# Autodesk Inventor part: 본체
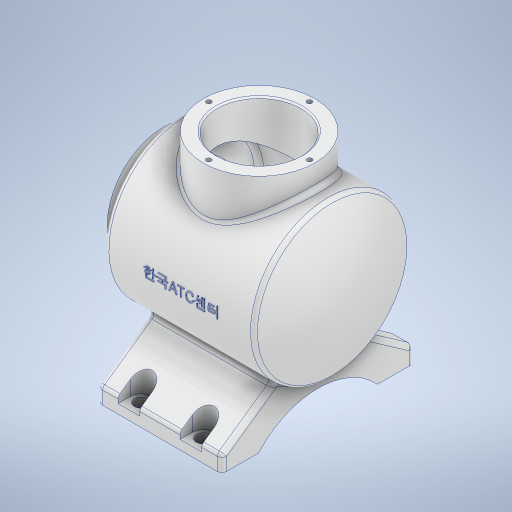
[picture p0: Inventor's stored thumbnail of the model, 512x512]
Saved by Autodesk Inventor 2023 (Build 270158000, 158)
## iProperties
Created: 2023-12
Part Number: 본체
Material: 알루미늄 6061
Document SubType Name: Modeling
Designer: asung
Density: 2.7 g/cm^3
Appearance: 알루미늄 - 평지
Mass: 1296.7 g
Surface Area: 1060.42 cm^2
Volume: 480.26 cm^3
Author: asung
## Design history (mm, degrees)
sketch "스케치2"
  geometry: L1 (0, 0)-(108, 0); L2 (0, 0)-(0, 50); L3 (0, 50)-(96.336, 50); L4 (108, 0)-(-5, 0); A1 r 113 centre (-5, 0) between (108, 0) and (96.336, 50)
  constraints: 8 end point, 2 horizontal, 2 point on circle, 1 centre point, 1 coincident, 1 perpendicular, 1 vertical
  dimensions: "d6" = 108 distance of L1.start L1.end; "d7" = 100 diameter of L3 L1; "d9" = 226 diameter of A1
revolve "회전2" sketch "스케치2" stored, may be unused: angle "d10" = 90 deg
fillet "모깎기1" dims "d11" = 3
sketch "스케치3"
  geometry: C1 r 36 at (0, 0); 1 further point
  constraints: 1 centre point, 1 coincident
  dimensions: "d12" = 72 diameter of C1
extrude "돌출1" join sketch "스케치3" distance "d13" = 12; taper "d14" = 0 deg
fillet "모깎기2" dims "d15" = 3
node "작업 평면1"
sketch "스케치4"
  geometry: L1 (0, 0)-(0, -77); L2 (0, -77)-(-62, -77); L3 (0, -77)-(62, -77); L4 (-62, -77)-(-62, -67); L5 (62, -77)-(62, -67); L6 (62, -67)-(24.84, -40.98); L7 (-62, -67)-(-25.197, -41.23); L8 (0, -77)-(0, -60); L9 (0, -77)-(38.5, -77); L10 (0, -77)-(-38.5, -77); C1 r 50 at (0, 0) reference; A1 r 52.096 centre (0, -112.096) between (38.5, -77) and (-38.5, -77); 3 further points
  constraints: 20 end point, 3 point on circle, 3 point on line, 3 vertical, 2 horizontal, 1 centre point
  dimensions: "d17" = 77 distance of L1.start L1.end; "d18" = 62 distance of L1.end L2.end; "d19" = 62 distance of L1.end L3.end; "d20" = 10 distance of L2.end L4.end; "d21" = 10 distance of L3.end L5.end; "d22" = 55 deg angle of L5 L6; "d23" = 55 deg angle of L4 L7; "d24" = 17 distance of L1.end L8.end; "d25" = 38.5 distance of L1.end L9.end; "d26" = 38.5 distance of L1.end L10.end
extrude "돌출2" join sketch "스케치4" distance "d27" = 80; taper "d28" = 0 deg
node "작업 평면2"
sketch "스케치5"
  geometry: L1 (-5, 12)-(86.454, 12) reference; L2 (-20, 98)-(-20, 26) reference; L3 (-20, 62)-(42, 62); C1 r 36 at (42, 62); 1 further point
  constraints: 2 end point, 1 centre point, 1 coincident, 1 horizontal, 1 midpoint
  dimensions: "d30" = 62 distance of L3.start L3.end; "d31" = 72 diameter of C1
extrude "돌출3" join sketch "스케치5" stored distance "d32" = 80; taper "d33" = 0 deg
sketch "스케치6"
  geometry: L1 (0, 23.5)-(0, -11.806) reference; L2 (0, 23.5)-(0, 15.5); L3 (0, 15.5)-(20, 15.5); L4 (0, 23.5)-(80, 23.5) reference; L5 (20, 15.5)-(60, 15.5); 1 further point
  constraints: 6 end point, 2 horizontal, 1 point on line
  dimensions: "d34" = 8 distance of L1.start L2.end; "d35" = 20 distance of L2.end L3.end; "d37" = 40 distance of L3.end L5.end
hole "구멍1" sketch "스케치6" at (20, 15.5), (60, 15.5) diameter "d38" = 9; stored, may be unused: countersink angle "d42" = 90 deg, drill point angle "d44" = 0 deg; dims "d39" = 8, "d40" = 4, "d41" = 2, "d43" = 6
sketch "스케치7"
  geometry: C1 r 4.5 at (0, 0) reference; 1 further point
  node "투영된 루프1"
sketch "스케치8"
  geometry: L1 (94.454, -50)-(88, -50) reference; L2 (88, -50)-(88, -60) reference; L3 (88, -60)-(8, -60) reference; L4 (8, -60)-(8, -50) reference; L5 (8, -50)-(3, -50) reference; L6 (0, -47)-(0, -39) reference; L7 (-3, -36)-(-12, -36) reference; L8 (-12, -36)-(-12, 36) reference; L9 (-12, 36)-(-3, 36) reference; L10 (0, 39)-(0, 47) reference; L11 (3, 50)-(14, 50) reference; L12 (14, 50)-(14, 65) reference; L13 (14, 65)-(86, 65) reference; L14 (86, 65)-(86, 50) reference; L15 (86, 50)-(94.454, 50) reference; L16 (89.916, 43)-(79, 43); L17 (21, 43)-(10, 43); L18 (7, 43)-(7, 39); L19 (79, 43)-(21, 43); L20 (7, 40)-(7, 0); L21 (7, 0)-(101, 0); A1 r 3 centre (94.454, 47) between (97.166, 48.282) and (94.454, 50) reference; A2 r 113 centre (-5, 0) between (97.166, -48.282) and (97.166, 48.282) reference; A3 r 3 centre (94.454, -47) between (94.454, -50) and (97.166, -48.282) reference; A4 r 3 centre (3, -47) between (0, -47) and (3, -50) reference; A5 r 3 centre (-3, -39) between (0, -39) and (-3, -36) reference; A6 r 3 centre (-3, 39) between (-3, 36) and (0, 39) reference; A7 r 3 centre (3, 47) between (3, 50) and (0, 47) reference; A8 r 106 centre (-5, 0) between (101, 0) and (92.68, 41.165); A9 r 3 centre (10, 40) between (10, 43) and (7, 40); A10 r 3 centre (89.916, 40) between (92.68, 41.165) and (89.916, 43); 3 further points
  constraints: 12 end point, 7 point on circle, 4 tangent, 3 centre point, 3 point on line, 1 horizontal, 1 vertical
  dimensions: "d45" = 3 radius of A9; "d46" = 7 radial gap between concentric circles of A2 A8; "d47" = 3 radius of A10 (derived); "d48" = 7 distance between parallel lines of L17 L11; "d49" = 7 distance between parallel lines of L10 L20
revolve "회전3" sketch "스케치8" stored, may be unused: angle "d50" = 90 deg
sketch "스케치9"
  geometry: 1 further point
hole "구멍2" sketch "스케치9" at (0, 0) diameter "d51" = 54; stored, may be unused: countersink angle "d55" = 90 deg, drill point angle "d57" = 0 deg; dims "d52" = 6, "d53" = 4, "d54" = 2, "d56" = 19
chamfer "모따기1" distance "d58" = 1; stored, may be unused: second distance "d59" = 2, angle "d60" = 45 deg
sketch "스케치10"
  geometry: C1 r 36 at (0, 0) reference; 1 further point
hole "구멍3" sketch "스케치10" at (0, 0) diameter "d61" = 54; stored, may be unused: countersink angle "d65" = 90 deg, drill point angle "d67" = 0 deg; dims "d62" = 6, "d63" = 4, "d64" = 2, "d66" = 25
sketch "스케치11"
  geometry: L1 (21.909, 15.78)-(-21.909, 15.78) reference; A1 r 27 centre (0, 0) between (21.909, 15.78) and (-21.909, 15.78) reference; 1 further point
hole "구멍4" sketch "스케치11" at (0, 0) diameter "d68" = 54; stored, may be unused: countersink angle "d72" = 90 deg, drill point angle "d74" = 0 deg; dims "d69" = 6, "d70" = 4, "d71" = 2, "d73" = 25
chamfer "모따기2" distance "d75" = 1; stored, may be unused: second distance "d76" = 2, angle "d77" = 45 deg
fillet "모깎기3" dims "d78" = 3
node "작업 평면3"
sketch "스케치12"
  geometry: L1 (-60.168, 36)-(-60.168, -36) reference; 2 further points
  constraints: 1 horizontal alignment, 1 other
  dimensions: "d79" = 62 distance from line of L1 point (1.832, 0)
feature "엠보싱1" sketch "스케치12" dims "d80" = 0.5, "d81" = 0
sketch "스케치13"
  geometry: L1 (0, 32.5)-(0, -32.5); A1 r 32.5 centre (0, 0) between (0, 32.5) and (0, -32.5); 1 further point
  constraints: 2 end point, 2 point on circle, 1 centre point, 1 coincident, 1 vertical
  dimensions: "d82" = 65 diameter of A1
hole "구멍5" sketch "스케치13" at (0, 32.5) diameter "d83" = 3.242; stored, may be unused: countersink angle "d87" = 90 deg, drill point angle "d89" = 118 deg; dims "d84" = 8, "d85" = 4, "d86" = 2, "d88" = 10
sketch "스케치14"
  geometry: L1 (0, 32.5)-(0, -32.5); C1 r 36 at (0, 0) reference; C2 r 28 at (0, 0) reference; A1 r 32.5 centre (0, 0) between (0, 32.5) and (0, -32.5); 1 further point
  constraints: 2 end point, 2 point on circle, 1 centre point, 1 coincident, 1 vertical
  dimensions: "d93" = 65 diameter of A1
hole "구멍6" sketch "스케치14" at (0, 32.5) diameter "d94" = 3.242; stored, may be unused: countersink angle "d98" = 90 deg, drill point angle "d100" = 118 deg; dims "d95" = 8, "d96" = 4, "d97" = 2, "d99" = 10
node "작업 평면4"
sketch "스케치15"
  geometry: L1 (80, -100.5)-(0, -100.5) reference; L2 (0, -100.5)-(0, -70.517) reference; L3 (0, -70.517)-(80, -70.517) reference; L4 (80, -70.517)-(80, -100.5) reference; L5 (0, 23.5)-(80, 23.5) reference; L6 (80, 23.5)-(80, -6.483) reference; L7 (80, -6.483)-(0, -6.483) reference; L8 (0, -6.483)-(0, 23.5) reference; L9 (13, 15.5)-(13, 23.5); L10 (0, 23.5)-(80, 23.5) reference; L11 (27, 15.5)-(27, 23.5); L12 (53, 15.5)-(53, 23.5); L13 (67, 15.5)-(67, 23.5); C1 r 4.5 at (20, 15.5) reference; C2 r 4.5 at (60, 15.5) reference; A1 r 7 centre (20, 15.5) between (13, 15.5) and (27, 15.5); A2 r 7 centre (60, 15.5) between (53, 15.5) and (67, 15.5); 5 further points
  constraints: 8 end point, 4 perpendicular, 4 point on circle, 4 point on line, 2 centre point, 2 coincident
  dimensions: "d105" = 14 diameter of A1; "d106" = 14 diameter of A2
extrude "돌출4" cut sketch "스케치15" distance "d107" = 15; taper "d108" = 0 deg
fillet "모깎기4" dims "d109" = 3
fillet "모깎기5" dims "d110" = 3
fillet "모깎기6" dims "d111" = 3
node "솔리드2"
pattern_circular "원형 패턴1" dims angle "d91" = 360 deg
pattern_circular "원형 패턴2" dims angle "d102" = 360 deg
mirror "미러1"
node "투영된 루프2"
node "투영된 루프3"
node "투영된 루프4"
node "절단 모서리 투영1"
node "절단 모서리 투영2"
node "절단 모서리 투영3"
feature "A9D066F2-1C7D-4E18-AEED-F7BC21143FA4" dims "d38" = 9, "d39" = 8, "d40" = 4, "d41" = 2, "d42" = 90 deg, "d43" = 6, "d44" = 0
other parameters: "d29" = -142, "d104" = -6
